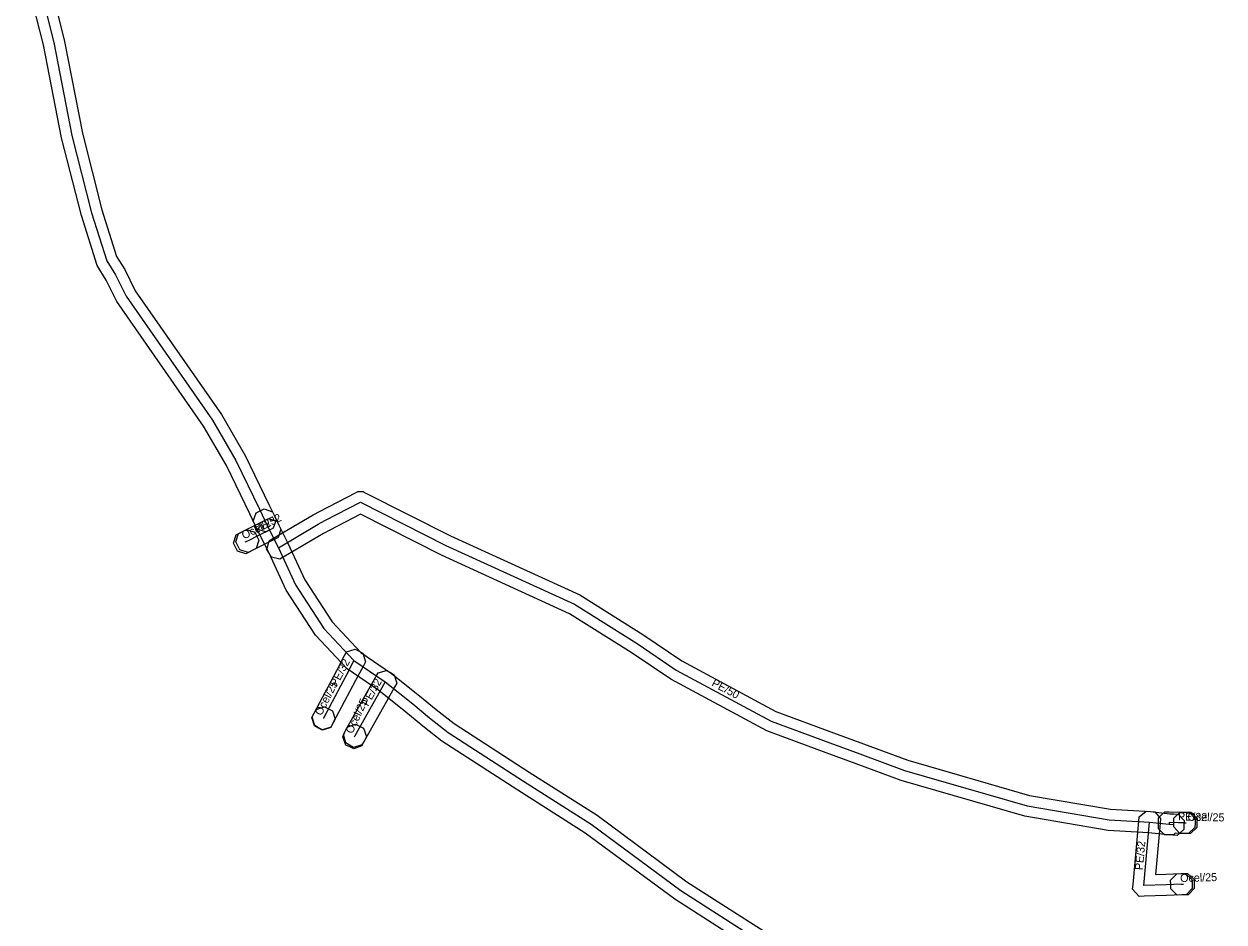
# Model space of a CAD drawing. Extents: x -678368 to -678136, y -1057358 to -1057053.
# Drawn here: x -678259.4 to -678147, y -1057221.1 to -1057136.9 of the extents above; entities that cross this region are included whole.
import ezdxf

# ---------------------------------------------------------------- set-up
doc = ezdxf.new("R2010")
doc.units = 0
for name, color, linetype in [('1', 7, 'Continuous'), ('24', 7, 'Continuous'), ('30', 7, 'Continuous')]:
    doc.layers.add(name, color=color, linetype=linetype)

msp = doc.modelspace()

# ---------------------------------------------------------------- linework, layer by layer
at = {"layer": '1'}
for points in [[(-678257.54, -1057130.97), (-678255.66, -1057138.42), (-678253.96, -1057147.14), (-678252.14, -1057154.33), (-678250.76, -1057158.7), (-678249.98, -1057159.93), (-678249.01, -1057161.91), (-678240.94, -1057173.51), (-678238.7, -1057177.35), (-678236.48, -1057181.95), (-678235.97, -1057182.99), (-678235.79, -1057183.37), (-678236.07, -1057184.15), (-678236.44, -1057184.33), (-678236.81, -1057184.51), (-678237.59, -1057184.24), (-678237.77, -1057183.86), (-678238.28, -1057182.82), (-678240.46, -1057178.29), (-678242.62, -1057174.59), (-678250.73, -1057162.93), (-678251.72, -1057160.91), (-678252.58, -1057159.54), (-678254.06, -1057154.87), (-678255.92, -1057147.58), (-678257.62, -1057138.86), (-678259.44, -1057131.65)], [(-678187.6, -1057225.88), (-678198.45, -1057218.92), (-678206.86, -1057212.72), (-678213.17, -1057208.69), (-678220.27, -1057204.11), (-678222.07, -1057202.71), (-678223.64, -1057201.39), (-678226.18, -1057199.36), (-678229.16, -1057197.33), (-678232.13, -1057194.17), (-678234.87, -1057189.97), (-678236.5, -1057186.43), (-678237.34, -1057184.77), (-678237.78, -1057183.86), (-678237.95, -1057183.49), (-678237.68, -1057182.71), (-678237.31, -1057182.53), (-678236.94, -1057182.35), (-678236.15, -1057182.62), (-678235.97, -1057183), (-678235.54, -1057183.89), (-678234.7, -1057185.55), (-678233.11, -1057189), (-678230.55, -1057192.93), (-678227.86, -1057195.8), (-678224.98, -1057197.76), (-678222.38, -1057199.85), (-678220.81, -1057201.15), (-678219.11, -1057202.47), (-678212.09, -1057207.01), (-678205.72, -1057211.06), (-678197.31, -1057217.28), (-678186.36, -1057224.3)]]:
    msp.add_lwpolyline(points, dxfattribs=at)
for points in [[(-678236.47, -1057185.34), (-678236.11, -1057185.13), (-678232.34, -1057182.9), (-678231.69, -1057182.56), (-678228.36, -1057180.84), (-678228.14, -1057180.73), (-678227.66, -1057180.73), (-678227.45, -1057180.84), (-678219.46, -1057184.88), (-678207.35, -1057190.41), (-678201.43, -1057194.13), (-678197.79, -1057196.59), (-678188.99, -1057201.32), (-678183.58, -1057203.32), (-678180.76, -1057204.36), (-678176.6, -1057205.9), (-678165.19, -1057209.19), (-678157.62, -1057210.49), (-678153.86, -1057210.69), (-678152.04, -1057210.91), (-678151.68, -1057210.92), (-678151.27, -1057210.95), (-678150.71, -1057211.56), (-678150.73, -1057211.97), (-678150.75, -1057212.39), (-678151.37, -1057212.94), (-678151.78, -1057212.92), (-678152.2, -1057212.9), (-678154.04, -1057212.69), (-678157.84, -1057212.48), (-678165.63, -1057211.15), (-678177.22, -1057207.8), (-678181.46, -1057206.24), (-678184.27, -1057205.2), (-678189.81, -1057203.14), (-678198.83, -1057198.31), (-678202.53, -1057195.81), (-678208.31, -1057192.17), (-678220.32, -1057186.68), (-678227.9, -1057182.85), (-678230.78, -1057184.34), (-678231.37, -1057184.65), (-678235.09, -1057186.85), (-678235.45, -1057187.06), (-678236.25, -1057186.86), (-678236.46, -1057186.5), (-678236.67, -1057186.14)], [(-678235.62, -1057185.04), (-678235.99, -1057185.22), (-678236.94, -1057185.7), (-678238.05, -1057186.26), (-678238.42, -1057186.44), (-678239.21, -1057186.18), (-678239.39, -1057185.81), (-678239.58, -1057185.44), (-678239.32, -1057184.66), (-678238.95, -1057184.47), (-678237.83, -1057183.91), (-678236.89, -1057183.44), (-678236.52, -1057183.25), (-678235.73, -1057183.51), (-678235.55, -1057183.88), (-678235.36, -1057184.25)], [(-678237.68, -1057186.07), (-678238.05, -1057186.26), (-678238.28, -1057186.37), (-678238.65, -1057186.56), (-678239.44, -1057186.3), (-678239.62, -1057185.93), (-678239.81, -1057185.56), (-678239.55, -1057184.77), (-678239.18, -1057184.58), (-678238.95, -1057184.47), (-678238.58, -1057184.28), (-678237.79, -1057184.54), (-678237.6, -1057184.92), (-678237.42, -1057185.28)], [(-678227.43, -1057196.67), (-678227.63, -1057197.04), (-678228.36, -1057198.43), (-678230.48, -1057202.43), (-678230.67, -1057202.8), (-678231.46, -1057203.04), (-678231.83, -1057202.85), (-678232.19, -1057202.65), (-678232.44, -1057201.86), (-678232.24, -1057201.5), (-678230.13, -1057197.49), (-678229.39, -1057196.1), (-678229.2, -1057195.74), (-678228.41, -1057195.49), (-678228.04, -1057195.69), (-678227.68, -1057195.88)], [(-678224.51, -1057198.69), (-678224.71, -1057199.05), (-678225.47, -1057200.4), (-678227.56, -1057204.1), (-678227.76, -1057204.47), (-678228.56, -1057204.69), (-678228.92, -1057204.48), (-678229.28, -1057204.28), (-678229.5, -1057203.48), (-678229.3, -1057203.12), (-678227.21, -1057199.41), (-678226.45, -1057198.07), (-678226.25, -1057197.71), (-678225.45, -1057197.49), (-678225.09, -1057197.69), (-678224.73, -1057197.89)], [(-678230.28, -1057202.05), (-678230.47, -1057202.42), (-678230.49, -1057202.45), (-678230.68, -1057202.82), (-678231.47, -1057203.07), (-678231.84, -1057202.88), (-678232.2, -1057202.69), (-678232.46, -1057201.9), (-678232.27, -1057201.53), (-678232.25, -1057201.5), (-678232.06, -1057201.14), (-678231.27, -1057200.88), (-678230.9, -1057201.07), (-678230.53, -1057201.26)], [(-678227.35, -1057203.66), (-678227.52, -1057204.04), (-678227.58, -1057204.17), (-678227.76, -1057204.54), (-678228.54, -1057204.83), (-678228.91, -1057204.65), (-678229.29, -1057204.48), (-678229.57, -1057203.7), (-678229.4, -1057203.32), (-678229.33, -1057203.19), (-678229.16, -1057202.81), (-678228.38, -1057202.53), (-678228, -1057202.71), (-678227.63, -1057202.88)], [(-678150.52, -1057218.51), (-678150.94, -1057218.52), (-678152.36, -1057218.56), (-678154.47, -1057218.63), (-678154.92, -1057218.65), (-678155.23, -1057218.32), (-678155.54, -1057217.99), (-678155.49, -1057217.54), (-678154.95, -1057211.6), (-678154.91, -1057211.19), (-678154.27, -1057210.66), (-678153.86, -1057210.69), (-678153.45, -1057210.73), (-678152.92, -1057211.37), (-678152.95, -1057211.78), (-678153.4, -1057216.6), (-678152.42, -1057216.57), (-678151, -1057216.52), (-678150.59, -1057216.51), (-678149.98, -1057217.07), (-678149.97, -1057217.49), (-678149.95, -1057217.9)], [(-678151.25, -1057212.75), (-678151.54, -1057212.74), (-678151.71, -1057212.9), (-678152.12, -1057212.9), (-678152.54, -1057212.9), (-678153.12, -1057212.32), (-678153.12, -1057211.9), (-678153.12, -1057211.73), (-678153.12, -1057211.31), (-678152.82, -1057211.01), (-678152.52, -1057210.72), (-678152.1, -1057210.73), (-678151.21, -1057210.75), (-678150.66, -1057210.76), (-678150.25, -1057210.77), (-678149.68, -1057211.37), (-678149.69, -1057211.78), (-678149.7, -1057212.2), (-678150.3, -1057212.77), (-678150.71, -1057212.76)], [(-678151.08, -1057210.75), (-678150.66, -1057210.76), (-678150.48, -1057210.76), (-678150.07, -1057210.77), (-678149.5, -1057211.37), (-678149.51, -1057211.79), (-678149.52, -1057212.2), (-678150.11, -1057212.77), (-678150.53, -1057212.76), (-678150.71, -1057212.76), (-678151.12, -1057212.75), (-678151.69, -1057212.15), (-678151.69, -1057211.74), (-678151.68, -1057211.32)], [(-678151.41, -1057216.53), (-678151, -1057216.52), (-678150.8, -1057216.51), (-678150.39, -1057216.5), (-678149.78, -1057217.07), (-678149.77, -1057217.48), (-678149.76, -1057217.9), (-678150.33, -1057218.5), (-678150.74, -1057218.51), (-678150.94, -1057218.52), (-678151.35, -1057218.53), (-678151.95, -1057217.96), (-678151.97, -1057217.55), (-678151.98, -1057217.14)]]:
    msp.add_lwpolyline(points, close=True, dxfattribs=at)
at = {"layer": '24'}
for points in [[(-678258.49, -1057131.31), (-678256.64, -1057138.64), (-678254.94, -1057147.36), (-678253.1, -1057154.6), (-678251.67, -1057159.12), (-678250.85, -1057160.42), (-678249.87, -1057162.42), (-678241.78, -1057174.05), (-678239.58, -1057177.82), (-678237.38, -1057182.39), (-678236.87, -1057183.43)], [(-678235.6, -1057185.99), (-678231.86, -1057183.77), (-678231.23, -1057183.45), (-678227.9, -1057181.73), (-678219.89, -1057185.78), (-678207.83, -1057191.29), (-678201.98, -1057194.97), (-678198.31, -1057197.45), (-678189.4, -1057202.23), (-678183.92, -1057204.26), (-678181.11, -1057205.3), (-678176.91, -1057206.85), (-678165.41, -1057210.17), (-678157.73, -1057211.48), (-678153.95, -1057211.69), (-678152.12, -1057211.9), (-678151.73, -1057211.92)], [(-678236.87, -1057183.43), (-678236.44, -1057184.33), (-678235.6, -1057185.99), (-678233.99, -1057189.48), (-678231.34, -1057193.55), (-678228.51, -1057196.57), (-678225.58, -1057198.56), (-678223.01, -1057200.62), (-678221.44, -1057201.93), (-678219.69, -1057203.29), (-678212.63, -1057207.85), (-678206.29, -1057211.89), (-678197.88, -1057218.1), (-678186.98, -1057225.09)], [(-678236.44, -1057184.33), (-678237.39, -1057184.8), (-678238.5, -1057185.36)], [(-678238.5, -1057185.36), (-678238.73, -1057185.48)], [(-678228.51, -1057196.57), (-678229.24, -1057197.96), (-678231.36, -1057201.96)], [(-678225.58, -1057198.56), (-678226.34, -1057199.91), (-678228.43, -1057203.61)], [(-678231.36, -1057201.96), (-678231.38, -1057201.99)], [(-678228.43, -1057203.61), (-678228.49, -1057203.75)], [(-678150.97, -1057217.52), (-678152.39, -1057217.56), (-678154.5, -1057217.63), (-678153.95, -1057211.69)], [(-678150.69, -1057211.76), (-678151.23, -1057211.75), (-678152.12, -1057211.73), (-678152.12, -1057211.9)], [(-678150.69, -1057211.76), (-678150.51, -1057211.76)], [(-678150.97, -1057217.52), (-678150.77, -1057217.51)]]:
    msp.add_lwpolyline(points, dxfattribs=at)

# ---------------------------------------------------------------- texts
at = {"layer": '30'}
for s, rotation, p in [('Ocel/25', 26.665, (-678238.81, -1057185.22)), ('PE/32', 26.6473, (-678237.67, -1057184.65)), ('PE/32', 62.1336, (-678230.14, -1057199.07)), ('PE/32', 60.6041, (-678227.2, -1057200.89)), ('PE/50', 331.7875, (-678195.06, -1057198.89)), ('Ocel/25', 62.7004, (-678231.57, -1057201.78)), ('Ocel/25', 65.0067, (-678228.66, -1057203.48)), ('PE/32', 358.7141, (-678151.29, -1057211.54)), ('Ocel/25', 358.7199, (-678150.4, -1057211.56)), ('PE/32', 84.7213, (-678154.59, -1057216.22)), ('Ocel/25', 1.7357, (-678151.07, -1057217.32))]:
    msp.add_text(s, height=0.75, rotation=rotation, dxfattribs=at).set_placement(p)

doc.saveas('drawing.dxf')
